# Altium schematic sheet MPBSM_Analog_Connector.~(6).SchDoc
size 431 x 279 mm; Date: Not shown in title block; ApprovedBy: Not shown in title block; CheckedBy: Not shown in title block; Author: Not shown in title block; CompanyName: Not shown in title block; Engineer: Not shown in title block; Organization: Not shown in title block; Address1: Not shown in title block; Address2: Not shown in title block; Address3: Not shown in title block; Address4: Not shown in title block; DocumentNumber: 1; Revision: Use project parameter SCH_Rev; SheetNumber: 2; SheetTotal: 3; PageSetup: Record=PageOptions¦CenterHorizontal=True¦CenterVertical=True¦PrintScale=1.00¦XCorrection=1.00¦YCorrection=1.00¦PrintKind=0¦BorderSize=5000000¦LeftOffset=0¦BottomOffset=0¦Orientation=2¦PaperLength=1000¦PaperWidth=1000¦Scale=100¦PaperSource=15¦PrintQuality=600¦MediaType=1¦DitherType=10¦PaperKind=Letter¦PrintScaleMode=1
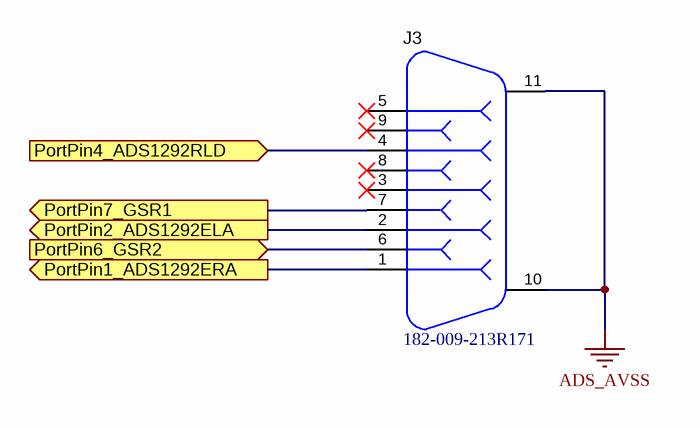
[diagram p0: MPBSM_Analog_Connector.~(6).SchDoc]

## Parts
J3  182-009-213R171  [NORCOMP_182-009-213R171]

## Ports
PortPin1_ADS1292ERA (out), PortPin2_ADS1292ELA (out), PortPin4_ADS1292RLD (in), PortPin6_GSR2 (in), PortPin7_GSR1 (out)

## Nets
ADS_AVSS: J3.10 J3.11
PortPin1_ADS1292ERA: J3.1 ; port PortPin1_ADS1292ERA
PortPin2_ADS1292ELA: J3.2 ; port PortPin2_ADS1292ELA
PortPin4_ADS1292RLD: J3.4 ; port PortPin4_ADS1292RLD
PortPin6_GSR2: J3.6 ; port PortPin6_GSR2
PortPin7_GSR1: J3.7 ; port PortPin7_GSR1

Not connected (* = marked no-connect by the designer): J3 3* 5* 8* 9*

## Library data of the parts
J3 = 182-009-213R171: CONN DB9 FEMALE R/A SOLDER TH; Manufacturer: NorComp; SymbolCreator: a0412235; CompType: Connector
